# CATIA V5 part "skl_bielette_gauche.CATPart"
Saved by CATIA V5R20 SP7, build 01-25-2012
Part number: skl_bielette_gauche
Publications: "Axe_pivot_biellette_gauche_bras_gauche", "Axe_pivot_biellette_gauche_levier", "Plan.1"
Bounding box of the stored display mesh (mm): x -200 to -68.75, y 700 to 772.62, z 0 to 20
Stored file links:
  U:\IAO\thinkmotion catia2\skl_bielette_gauche.CATPart
  U:\IAO\thinkmotion catia2\skl_862_adubourgno.CATProduct
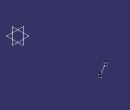
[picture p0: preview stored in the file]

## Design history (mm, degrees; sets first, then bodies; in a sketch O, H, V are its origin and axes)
Set1
  Point1 "B2": linked copy from another document
  Point2 "E": linked copy from another document
  Plane1: linked copy from another document
Set2
  Line1: type PtPt, FirstPoint Point1, SecondPoint Point2
  Line2 "Axe_pivot_biellette_gauche_levier": type Normal, RefPoint Point1, RefSkin Plane1, Start 0, End 20
  Line3 "Axe_pivot_biellette_gauche_bras_gauche": type Normal, RefPoint Point2, RefSkin Plane1, Start 0, End 20
Body1 (main body)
